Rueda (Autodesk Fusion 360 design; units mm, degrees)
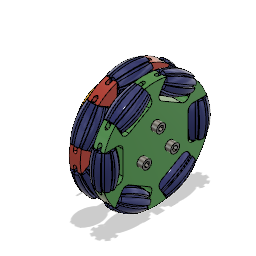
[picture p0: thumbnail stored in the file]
sketch "Sketch1" plane through (0, 0, 0) normal (1, 0, 0) x axis (0, 0, -1)
  dimension "d1" = 96
extrude "Extrude1" new body sketch "Sketch1" along normal blind 10
sketch "Sketch2" plane through (0, 0, -15) normal (0, 0, 1) x axis (1, 0, 0)
extrude "Extrude2" cut sketch "Sketch2" against normal blind 5
fillet "Fillet1" radius 1.5
fillet "Fillet2" radius 1.5
mirror "Mirror1"
circular_pattern "C-Pattern1" TotalAngle 360
sketch "Sketch1" plane through (0, 0, 0) normal (1, 0, 0) x axis (0, 0, -1)
copy_paste_bodies "CopyPasteBodies1"
position "Position1"
sketch "Sketch1" plane through (10, 0, 0) normal (1, 0, 0) x axis (0, 0, -1)
  dimension "d21" = 40
extrude "Extrude3" add sketch "Sketch1" along normal blind 12
sketch "Sketch2" plane through (22, 0, 0) normal (1, 0, 0) x axis (0, 0, -1)
  dimension "d24" = 8.66
  dimension "d25" = 8.66
  dimension "d26" = 3.9
  dimension "d27" = 3.9
sketch "Sketch3" plane through (0, 0, 0) normal (-1, 0, 0) x axis (0, 0, 1)
  dimension "d30" = 40
extrude "Extrude1" cut sketch "Sketch3" against normal blind 3
sketch "Sketch4" plane through (10, 0, 0) normal (1, 0, 0) x axis (0, 0, -1)
  dimension "d33" = 8.66
  dimension "d34" = 3.9
  dimension "d36" = 360
extrude "Extrude2" cut sketch "Sketch4" against normal blind 7
move "Move1"
sketch "Sketch5" plane through (0, 0, 0) normal (-1, 0, 0) x axis (0, 0, 1)
  dimension "d39" = 20
extrude "Extrude4" add sketch "Sketch5" along normal blind 16
extrude "Extrude5" cut sketch "Sketch2" against normal blind 13
sketch "Sketch6" plane through (-16, 0, 0) normal (-1, 0, 0) x axis (0, 0, 1)
  circle C1 centre (0, 0) radius 10
  circle C2 centre (0, 0) radius 7.4998
  dimension "d44" diameter C2 = 14.9996
extrude "Extrude6" add sketch "Sketch6" profile of C2 along normal blind 9
sketch "Sketch7" plane through (-25, 0, 0) normal (-1, 0, 0) x axis (0, 0, 1)
  circle C1 centre (0, 0) radius 7.4998
  circle C2 centre (0, 0) radius 3
extrude "Extrude7" cut sketch "Sketch7" profile of C2 against normal blind 10
sketch "Sketch1" plane through (0, 0, 0) normal (1, 0, 0) x axis (0, 0, -1)
  dimension "d53" = 30
revolve "Revolve1" sketch "Sketch1" AlongAngle 30
revolve "Revolve2" sketch "Sketch1" AlongAngle 45
circular_pattern "C-Pattern1" TotalAngle 360
sketch "Sketch3" plane through (0, 19.5, -33.775) normal (0, 0.5, -0.866) x axis (-1, 0, 0)
cylinder_primitive "CylinderPrimitive1" Height 30 Diameter 3
sketch "Sketch2" plane through (0, 0, 30) normal (0, 0, 1) x axis (1, 0, 0)
box_primitive "BoxPrimitive1" DistanceX 3 DistanceY 3 DistanceZ 3.5 OffsetDistanceX 0 OffsetDistanceY 0
fillet "Fillet1" radius 1.5
sketch "Sketch3" plane through (0, 0, 0) normal (0, 0, -1) x axis (-1, 0, 0)
box_primitive "BoxPrimitive2" DistanceX 3 DistanceY 3 DistanceZ 3.5 OffsetDistanceX 0 OffsetDistanceY 0
fillet "Fillet2" radius 1.5
joint "Assemble2" alignAngle 180 alignOffsetX 0 alignOffsetY 0 alignOffsetZ 0
circular_pattern "C-Pattern1" TotalAngle 360
mirror_component "MirrorComponent1"
derived_instance "DerivedInstance1"
move "Move1"
joint "Assemble3" alignAngle -180 alignOffsetX 0 alignOffsetY 0 alignOffsetZ 0
joint "Assemble4" alignAngle 0 alignOffsetX 0 alignOffsetY 0 alignOffsetZ 0
step "C-Pattern1" TotalAngle 360
sketch "Sketch1" plane through (0, 0, 0) normal (1, 0, 0) x axis (0, 0, -1)
  dimension "d144" = 1.5
revolve "Revolve1" sketch "Sketch1" AlongAngle 30
revolve "Revolve2" sketch "Sketch1" AlongAngle 45
circular_pattern "C-Pattern1" TotalAngle 360
joint "Assemble5" alignAngle 180 alignOffsetX 0 alignOffsetY 0 alignOffsetZ 0
step "C-Pattern2" TotalAngle 360
position "Position2"
joint "Assemble6" alignAngle 180 alignOffsetX 0 alignOffsetY 0 alignOffsetZ 0
position "Position3"
joint "Assemble7" alignAngle 180 alignOffsetX 0 alignOffsetY 0 alignOffsetZ 0
position "Position4"
joint "Assemble8" alignAngle 180 alignOffsetX 0 alignOffsetY 0 alignOffsetZ 0
position "Position5"
joint "Assemble9" alignAngle 180 alignOffsetX 0 alignOffsetY 0 alignOffsetZ 0
position "Position6"
joint "Assemble10" alignAngle 180 alignOffsetX 0 alignOffsetY 0 alignOffsetZ 0
position "Position7"
joint "Assemble11" alignAngle 0 alignOffsetX 0 alignOffsetY 0 alignOffsetZ 0
position "Position8"
joint "Assemble12" alignAngle 0 alignOffsetX 0 alignOffsetY 0 alignOffsetZ 0
position "Position9"
joint "Assemble13" alignAngle 0 alignOffsetX 0 alignOffsetY 0 alignOffsetZ 0
position "Position10"
joint "Assemble14" alignAngle 0 alignOffsetX 0 alignOffsetY 0 alignOffsetZ 0
position "Position11"
joint "Assemble15" alignAngle 0 alignOffsetX 0 alignOffsetY 0 alignOffsetZ 0
joint "Assemble16" alignAngle 0 alignOffsetX 0 alignOffsetY 0 alignOffsetZ 0
position "Position12"
cylinder_primitive "CylinderPrimitive1" Height 20 Diameter 3.9
sketch "Sketch2" plane through (20, 0, 0) normal (1, 0, 0) x axis (0, 0, -1)
  dimension "d297" = 8
extrude "Extrude1" add sketch "Sketch2" along normal blind 5
sketch "Sketch3" plane through (25, 0, 0) normal (1, 0, 0) x axis (0, 0, -1)
  dimension "d300" = 2
extrude "Extrude2" cut sketch "Sketch3" against normal blind 3
step "C-Pattern3" TotalAngle 360
position "Position13"
move "Move2"
sketch "Sketch4" plane through (22, 0, 0) normal (1, 0, 0) x axis (0, 0, -1)
  circle C1 centre (7.4998, -4.33) radius 1.95
  circle C2 centre (-8.66, 0) radius 1.95
  circle C3 centre (4.33, 7.4998) radius 1.95
  circle C4 centre (4.33, -7.4998) radius 1.95
  circle C5 centre (-7.4998, -4.33) radius 1.95
  circle C6 centre (0, 8.66) radius 1.95
  circle C7 centre (0, 0) radius 20
  circle C8 centre (4.33, 7.4998) radius 1.95
  circle C9 centre (-8.66, 0) radius 1.95
  circle C10 centre (4.33, -7.4998) radius 1.95
extrude "Extrude8" add sketch "Sketch4" profile of C2 C3 C4 C8 C9 C10 against normal blind 13
move "Move3"
sketch "Sketch1" plane through (0, 0, 0) normal (1, 0, 0) x axis (0, 0, -1)
  dimension "d343" = 50
  dimension "d344" = 15
  dimension "d347" = 13
  dimension "d348" = 23
  dimension "d351" = 360
  dimension "d353" = 360
extrude "Extrude1" new body sketch "Sketch1" along normal blind 2
joint "Assemble20" alignAngle 0 alignOffsetX 0 alignOffsetY 0 alignOffsetZ 0
hole "Hole1" HoleDepth 5 HoleDiameter 3 TipAngle 118
move "Move4"
move "Move1"
extrude "Extrude9" add of existing geometry blind 13
sketch "Sketch8" plane through (-62.2627, 0, 0) normal (1, 0, 0) x axis (0, 0, -1)
  dimension "d373" = 14.4338
  dimension "d374" = 5
  dimension "d375" = 5
  dimension "d376" = 5
  dimension "d424" = 360
extrude "Extrude10" cut sketch "Sketch8" against normal blind 13
sketch "Sketch9" plane through (-55.2627, 0, 0) normal (1, 0, 0) x axis (0, 0, -1)
extrude "Extrude3" add sketch "Sketch9" against normal blind 7
sketch "Sketch10" plane through (-55.2627, 0, 0) normal (1, 0, 0) x axis (0, 0, -1)
  dimension "d381" = 14.4338
  dimension "d382" = 5
  dimension "d383" = 5
  dimension "d384" = 5
extrude "Extrude4" cut sketch "Sketch10" against normal blind 7
move "Move5"
move "Move2"
move "Move6"
extrude "Extrude11" cut sketch "Sketch8" against normal blind 13
move "Move7"
joint "Assemble24" alignAngle 0 alignOffsetX 0 alignOffsetY 0 alignOffsetZ 0
joint "Assemble25" alignAngle -90 alignOffsetX 0 alignOffsetY 0 alignOffsetZ 0
joint "Assemble26" alignAngle 90 alignOffsetX 0 alignOffsetY 0 alignOffsetZ 0
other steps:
base_feature "Base Feature"
derived_base_feature "Derived Base Feature"
create_component "CreateComponent1"
create_component "CreateComponent2"
create_component "CreateComponent3"
create_component "CreateComponent6"
joint_origin "JointOrigin1" OffsetX 0 OffsetY 0 OffsetZ 0 AngleZ 0
joint_origin "JointOrigin1" OffsetX 0 OffsetY 0 OffsetZ 0 AngleZ 0
create_component "CreateComponent7"
joint_origin "JointOrigin1" OffsetX 0 OffsetY 0 OffsetZ 0 AngleZ 0
joint_origin "JointOrigin1" OffsetX 0 OffsetY 0 OffsetZ 0 AngleZ 0
joint_origin "JointOrigin2" OffsetX 0 OffsetY 0 OffsetZ 0 AngleZ 0
joint_origin "JointOrigin2" OffsetX 0 OffsetY 0 OffsetZ 0 AngleZ 0
create_component "CreateComponent8"
joint_origin "JointOrigin1" OffsetX 0 OffsetY 0 OffsetZ 0 AngleZ 0
joint_origin "JointOrigin2" OffsetX 0 OffsetY 0 OffsetZ 0 AngleZ 0
create_component "CreateComponent1"
joint_origin "JointOrigin2" OffsetX 0 OffsetY 0 OffsetZ 0 AngleZ 0
joint_origin "JointOrigin3" OffsetX 0 OffsetY 0 OffsetZ 0 AngleZ 0
joint_origin "JointOrigin3" OffsetX 0 OffsetY 0 OffsetZ 0 AngleZ 0
joint_origin "JointOrigin4" OffsetX 0 OffsetY 0 OffsetZ 0 AngleZ 0
joint_origin "JointOrigin4" OffsetX 0 OffsetY 0 OffsetZ 0 AngleZ 0
joint_origin "JointOrigin5" OffsetX 0 OffsetY 0 OffsetZ 0 AngleZ 0
joint_origin "JointOrigin5" OffsetX 0 OffsetY 0 OffsetZ 0 AngleZ 0
joint_origin "JointOrigin6" OffsetX 0 OffsetY 0 OffsetZ 0 AngleZ 0
joint_origin "JointOrigin6" OffsetX 0 OffsetY 0 OffsetZ 0 AngleZ 0
joint_origin "JointOrigin7" OffsetX 0 OffsetY 0 OffsetZ 0 AngleZ 0
joint_origin "JointOrigin3" OffsetX 0 OffsetY 0 OffsetZ 0 AngleZ 0
joint_origin "JointOrigin3" OffsetX 0 OffsetY 0 OffsetZ 0 AngleZ 0
joint_origin "JointOrigin4" OffsetX 0 OffsetY 0 OffsetZ 0 AngleZ 0
joint_origin "JointOrigin4" OffsetX 0 OffsetY 0 OffsetZ 0 AngleZ 0
joint_origin "JointOrigin5" OffsetX 0 OffsetY 0 OffsetZ 0 AngleZ 0
joint_origin "JointOrigin5" OffsetX 0 OffsetY 0 OffsetZ 0 AngleZ 0
joint_origin "JointOrigin6" OffsetX 0 OffsetY 0 OffsetZ 0 AngleZ 0
joint_origin "JointOrigin6" OffsetX 0 OffsetY 0 OffsetZ 0 AngleZ 0
joint_origin "JointOrigin7" OffsetX 0 OffsetY 0 OffsetZ 0 AngleZ 0
joint_origin "JointOrigin7" OffsetX 0 OffsetY 0 OffsetZ 0 AngleZ 0
joint_origin "JointOrigin2" OffsetX 0 OffsetY 0 OffsetZ 0 AngleZ 0
joint_origin "JointOrigin2" OffsetX 0 OffsetY 0 OffsetZ 0 AngleZ 0
create_component "CreateComponent9"
create_component "CreateComponent10"
joint_origin "JointOrigin1" OffsetX 0 OffsetY 0 OffsetZ 0 AngleZ 0
joint_origin "JointOrigin3" OffsetX 0 OffsetY 0 OffsetZ 0 AngleZ 0
joint_origin "JointOrigin7" OffsetX 0 OffsetY 0 OffsetZ 0 AngleZ 0
joint_origin "JointOrigin9" OffsetX 0 OffsetY 0 OffsetZ 0 AngleZ 0
joint_origin "JointOrigin8" OffsetX 0 OffsetY 0 OffsetZ 0 AngleZ 0
joint_origin "JointOrigin10" OffsetX 0 OffsetY 0 OffsetZ 0 AngleZ 0
joint_origin "JointOrigin9" OffsetX 0 OffsetY 0 OffsetZ 0 AngleZ 0
joint_origin "JointOrigin11" OffsetX 0 OffsetY 0 OffsetZ 0 AngleZ 0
